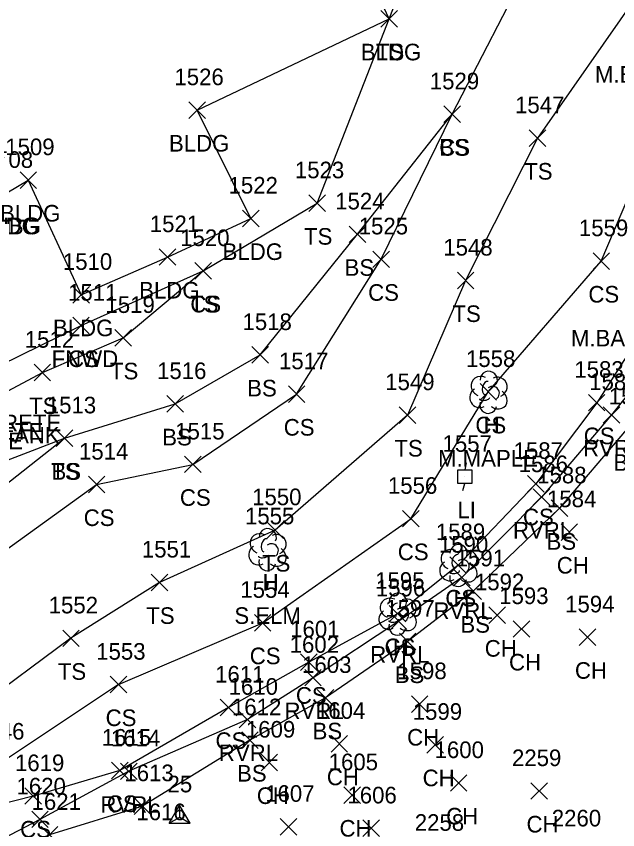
# Model space of a CAD drawing. Extents: x 1504228 to 1506103, y 437717 to 440106.
# Drawn here: x 1505258.5 to 1505331, y 438213.9 to 438311.9 of the extents above; entities that cross this region are included whole.
import ezdxf

# ---------------------------------------------------------------- set-up
doc = ezdxf.new("R2010")
doc.units = 0
for name, color, linetype in [('C_I', 7, 'Continuous'), ('CPSM', 7, 'Continuous'), ('L_A', 7, 'Continuous'), ('L_C', 7, 'Continuous'), ('L_I', 7, 'Continuous'), ('L_TIC', 7, 'Continuous'), ('LAWE', 7, 'Continuous'), ('LBC', 7, 'Continuous'), ('LELB', 7, 'Continuous'), ('LFNC', 7, 'Continuous'), ('LTD', 7, 'Continuous'), ('R_C', 7, 'Continuous'), ('U_A', 7, 'Continuous'), ('U_I', 7, 'Continuous'), ('ULP', 7, 'Continuous')]:
    doc.layers.add(name, color=color, linetype=linetype)

msp = doc.modelspace()

# ---------------------------------------------------------------- linework, layer by layer
at = {"layer": 'CPSM'}
for p, q in [((1505276.915, 438214.672), (1505278.165, 438216.837)), ((1505279.415, 438214.672), (1505278.165, 438216.837)), ((1505278.166, 438215.393), (1505278.165, 438216.837)), ((1505276.915, 438214.672), (1505278.166, 438215.393)), ((1505276.915, 438214.672), (1505279.415, 438214.672)), ((1505278.166, 438215.393), (1505278.166, 438215.393)), ((1505278.166, 438215.393), (1505279.415, 438214.672))]:
    msp.add_line(p, q, dxfattribs=at)
at = {"layer": 'L_TIC'}
for points in [[(1505302.41, 438310.599), (1505304.41, 438312.599)], [(1505304.41, 438310.599), (1505302.41, 438312.599)], [(1505302.41, 438310.599), (1505304.41, 438312.599)], [(1505304.41, 438310.599), (1505302.41, 438312.599)], [(1505279.282, 438299.604), (1505281.282, 438301.604)], [(1505281.282, 438299.604), (1505279.282, 438301.604)], [(1505310.019, 438299.105), (1505312.019, 438301.105)], [(1505312.019, 438299.105), (1505310.019, 438301.105)], [(1505310.019, 438299.105), (1505312.019, 438301.105)], [(1505312.019, 438299.105), (1505310.019, 438301.105)], [(1505320.287, 438296.225), (1505322.287, 438298.225)], [(1505322.287, 438296.225), (1505320.287, 438298.225)], [(1505258.92, 438291.172), (1505260.92, 438293.172)], [(1505260.92, 438291.172), (1505258.92, 438293.172)], [(1505293.747, 438288.385), (1505295.747, 438290.385)], [(1505295.747, 438288.385), (1505293.747, 438290.385)], [(1505285.75, 438286.544), (1505287.75, 438288.544)], [(1505287.75, 438286.544), (1505285.75, 438288.544)], [(1505298.605, 438284.634), (1505300.605, 438286.634)], [(1505300.605, 438284.634), (1505298.605, 438286.634)], [(1505275.691, 438281.896), (1505277.691, 438283.896)], [(1505277.691, 438281.896), (1505275.691, 438283.896)], [(1505301.441, 438281.622), (1505303.441, 438283.622)], [(1505303.441, 438281.622), (1505301.441, 438283.622)], [(1505327.992, 438281.411), (1505329.992, 438283.411)], [(1505329.992, 438281.411), (1505327.992, 438283.411)], [(1505280.008, 438280.222), (1505282.008, 438282.222)], [(1505282.008, 438280.222), (1505280.008, 438282.222)], [(1505280.008, 438280.222), (1505282.008, 438282.222)], [(1505282.008, 438280.222), (1505280.008, 438282.222)], [(1505311.638, 438279.068), (1505313.638, 438281.068)], [(1505313.638, 438279.068), (1505311.638, 438281.068)], [(1505265.3, 438277.353), (1505267.3, 438279.353)], [(1505267.3, 438277.353), (1505265.3, 438279.353)], [(1505265.273, 438273.64), (1505267.273, 438275.64)], [(1505267.273, 438273.64), (1505265.273, 438275.64)], [(1505265.273, 438273.64), (1505267.273, 438275.64)], [(1505267.273, 438273.64), (1505265.273, 438275.64)], [(1505270.354, 438272.157), (1505272.354, 438274.157)], [(1505272.354, 438272.157), (1505270.354, 438274.157)], [(1505286.866, 438270.097), (1505288.866, 438272.097)], [(1505288.866, 438270.097), (1505286.866, 438272.097)], [(1505260.614, 438267.97), (1505262.614, 438269.97)], [(1505262.614, 438267.97), (1505260.614, 438269.97)], [(1505314.372, 438265.647), (1505316.372, 438267.647)], [(1505316.372, 438265.647), (1505314.372, 438267.647)], [(1505291.268, 438265.376), (1505293.268, 438267.376)], [(1505293.268, 438265.376), (1505291.268, 438267.376)], [(1505276.623, 438264.195), (1505278.623, 438266.195)], [(1505278.623, 438264.195), (1505276.623, 438266.195)], [(1505327.434, 438264.347), (1505329.434, 438266.347)], [(1505329.434, 438264.347), (1505327.434, 438266.347)], [(1505304.643, 438262.855), (1505306.643, 438264.855)], [(1505306.643, 438262.855), (1505304.643, 438264.855)], [(1505329.226, 438262.864), (1505331.226, 438264.864)], [(1505331.226, 438262.864), (1505329.226, 438264.864)], [(1505263.276, 438260.061), (1505265.276, 438262.061)], [(1505265.276, 438260.061), (1505263.276, 438262.061)], [(1505263.276, 438260.061), (1505265.276, 438262.061)], [(1505265.276, 438260.061), (1505263.276, 438262.061)], [(1505278.753, 438256.916), (1505280.753, 438258.916)], [(1505280.753, 438256.916), (1505278.753, 438258.916)], [(1505267.157, 438254.486), (1505269.157, 438256.486)], [(1505269.157, 438254.486), (1505267.157, 438256.486)], [(1505320.109, 438254.57), (1505322.109, 438256.57)], [(1505322.109, 438254.57), (1505320.109, 438256.57)], [(1505320.774, 438252.978), (1505322.774, 438254.978)], [(1505322.774, 438252.978), (1505320.774, 438254.978)], [(1505322.954, 438251.628), (1505324.954, 438253.628)], [(1505324.954, 438251.628), (1505322.954, 438253.628)], [(1505305.017, 438250.366), (1505307.017, 438252.366)], [(1505307.017, 438250.366), (1505305.017, 438252.366)], [(1505288.682, 438248.994), (1505290.682, 438250.994)], [(1505290.682, 438248.994), (1505288.682, 438250.994)], [(1505324.135, 438248.753), (1505326.135, 438250.753)], [(1505326.135, 438248.753), (1505324.135, 438250.753)], [(1505310.747, 438244.782), (1505312.747, 438246.782)], [(1505312.747, 438244.782), (1505310.747, 438246.782)], [(1505311.194, 438243.278), (1505313.194, 438245.278)], [(1505313.194, 438243.278), (1505311.194, 438245.278)], [(1505274.731, 438242.689), (1505276.731, 438244.689)], [(1505276.731, 438242.689), (1505274.731, 438244.689)], [(1505312.563, 438241.629), (1505314.563, 438243.629)], [(1505314.563, 438241.629), (1505312.563, 438243.629)], [(1505303.42, 438238.919), (1505305.42, 438240.919)], [(1505305.42, 438238.919), (1505303.42, 438240.919)], [(1505303.566, 438238.011), (1505305.566, 438240.011)], [(1505305.566, 438238.011), (1505303.566, 438240.011)], [(1505315.449, 438238.742), (1505317.449, 438240.742)], [(1505317.449, 438238.742), (1505315.449, 438240.742)], [(1505287.172, 438237.832), (1505289.172, 438239.832)], [(1505289.172, 438237.832), (1505287.172, 438239.832)], [(1505318.376, 438237.075), (1505320.376, 438239.075)], [(1505320.376, 438237.075), (1505318.376, 438239.075)], [(1505326.323, 438236.077), (1505328.323, 438238.077)], [(1505328.323, 438236.077), (1505326.323, 438238.077)], [(1505264.066, 438235.954), (1505266.066, 438237.954)], [(1505266.066, 438235.954), (1505264.066, 438237.954)], [(1505304.646, 438235.558), (1505306.646, 438237.558)], [(1505306.646, 438235.558), (1505304.646, 438237.558)], [(1505292.736, 438233.076), (1505294.736, 438235.076)], [(1505294.736, 438233.076), (1505292.736, 438235.076)], [(1505293.241, 438231.21), (1505295.241, 438233.21)], [(1505295.241, 438231.21), (1505293.241, 438233.21)], [(1505269.798, 438230.377), (1505271.798, 438232.377)], [(1505271.798, 438230.377), (1505269.798, 438232.377)], [(1505269.798, 438230.377), (1505271.798, 438232.377)], [(1505271.798, 438230.377), (1505269.798, 438232.377)], [(1505294.746, 438228.78), (1505296.746, 438230.78)], [(1505296.746, 438228.78), (1505294.746, 438230.78)], [(1505283.045, 438227.619), (1505285.045, 438229.619)], [(1505285.045, 438227.619), (1505283.045, 438229.619)], [(1505306.096, 438228.028), (1505308.096, 438230.028)], [(1505308.096, 438228.028), (1505306.096, 438230.028)], [(1505285.327, 438226.151), (1505287.327, 438228.151)], [(1505287.327, 438226.151), (1505285.327, 438228.151)], [(1505285.64, 438223.685), (1505287.64, 438225.685)], [(1505287.64, 438223.685), (1505285.64, 438225.685)], [(1505296.415, 438223.25), (1505298.415, 438225.25)], [(1505298.415, 438223.25), (1505296.415, 438225.25)], [(1505307.962, 438223.13), (1505309.962, 438225.13)], [(1505309.962, 438223.13), (1505307.962, 438225.13)], [(1505287.976, 438220.99), (1505289.976, 438222.99)], [(1505289.976, 438220.99), (1505287.976, 438222.99)], [(1505269.947, 438220.02), (1505271.947, 438222.02)], [(1505271.947, 438220.02), (1505269.947, 438222.02)], [(1505271.047, 438219.927), (1505273.047, 438221.927)], [(1505273.047, 438219.927), (1505271.047, 438221.927)], [(1505310.8, 438218.522), (1505312.8, 438220.522)], [(1505312.8, 438218.522), (1505310.8, 438220.522)], [(1505320.491, 438217.554), (1505322.491, 438219.554)], [(1505322.491, 438217.554), (1505320.491, 438219.554)], [(1505259.492, 438216.948), (1505261.492, 438218.948)], [(1505261.492, 438216.948), (1505259.492, 438218.948)], [(1505297.947, 438217.058), (1505299.947, 438219.058)], [(1505299.947, 438217.058), (1505297.947, 438219.058)], [(1505272.677, 438215.738), (1505274.677, 438217.738)], [(1505274.677, 438215.738), (1505272.677, 438217.738)], [(1505260.327, 438214.137), (1505262.327, 438216.137)], [(1505262.327, 438214.137), (1505260.327, 438216.137)], [(1505290.292, 438213.251), (1505292.292, 438215.251)], [(1505292.292, 438213.251), (1505290.292, 438215.251)], [(1505300.263, 438213.06), (1505302.263, 438215.06)], [(1505302.263, 438213.06), (1505300.263, 438215.06)], [(1505261.485, 438212.279), (1505263.485, 438214.279)], [(1505263.485, 438212.279), (1505261.485, 438214.279)]]:
    msp.add_lwpolyline(points, dxfattribs=at)
at = {"layer": 'LAWE'}
msp.add_lwpolyline([(1505362.196, 438317.813), (1505351.384, 438297.395), (1505340.369, 438276.571), (1505330.226, 438263.864), (1505321.774, 438253.978), (1505312.194, 438244.278), (1505304.566, 438239.011), (1505294.241, 438232.21), (1505286.327, 438227.151), (1505272.047, 438220.927), (1505261.327, 438215.137), (1505255.057, 438211.857), (1505252.998, 438208.079)], dxfattribs=at)
at = {"layer": 'LBC'}
for points in [[(1505291.942, 438336.147), (1505251.464, 438317.946), (1505221.324, 438304.226), (1505215.361, 438301.39), (1505212.864, 438300.095), (1505216.768, 438291.382), (1505219.713, 438285.085), (1505224.136, 438275.747), (1505225.84, 438276.507), (1505226.05, 438276.605), (1505237.288, 438281.504), (1505257.323, 438290.638), (1505259.92, 438292.172), (1505266.3, 438278.353), (1505276.691, 438282.896), (1505286.75, 438287.544), (1505280.282, 438300.604), (1505303.41, 438311.599)], [(1505303.41, 438311.599), (1505291.942, 438336.147)]]:
    msp.add_lwpolyline(points, dxfattribs=at)
at = {"layer": 'LELB'}
for points in [[(1505345.996, 438335.597), (1505333.305, 438314.456), (1505321.287, 438297.225), (1505312.638, 438280.068), (1505305.643, 438263.855), (1505289.682, 438249.994), (1505275.731, 438243.689), (1505265.066, 438236.954), (1505253.57, 438228.442), (1505232.624, 438230.462), (1505221.792, 438235.116), (1505209.888, 438231.849), (1505203.313, 438230.133), (1505201.377, 438228.793), (1505195.715, 438225.539), (1505189.868, 438221.089), (1505181.214, 438212.467), (1505175.582, 438209.995), (1505180.422, 438196.297), (1505183.694, 438188.776), (1505173.648, 438207.305)], [(1505219.873, 438244.656), (1505224.212, 438246.435), (1505223.766, 438248.658), (1505222.665, 438251.446), (1505223.309, 438252.491), (1505228.977, 438251.314), (1505233.483, 438250.354), (1505246.941, 438254.407), (1505264.276, 438261.061), (1505277.623, 438265.195), (1505287.866, 438271.097), (1505299.605, 438285.634), (1505311.019, 438300.105), (1505320.782, 438319.021), (1505313.405, 438323.793)], [(1505270.798, 438231.377), (1505288.172, 438238.832), (1505306.017, 438251.366), (1505315.372, 438266.647), (1505328.992, 438282.411), (1505336.428, 438299.931), (1505351.563, 438320.448)], [(1505233.952, 438258.183), (1505245.998, 438260.651), (1505261.614, 438268.97), (1505271.354, 438273.157), (1505281.008, 438281.222), (1505294.747, 438289.385), (1505303.41, 438311.599), (1505306.612, 438319.703)], [(1505357.525, 438320.193), (1505347.775, 438299.58), (1505338.033, 438280.312), (1505328.434, 438265.347), (1505321.109, 438255.57), (1505311.747, 438245.782), (1505304.42, 438239.919), (1505293.736, 438234.076), (1505284.045, 438228.619), (1505270.947, 438221.02), (1505260.492, 438217.948), (1505254.014, 438216.283), (1505247.096, 438215.294)], [(1505365.146, 438316.099), (1505353.966, 438296.236), (1505341.915, 438275.153), (1505332.016, 438262.134), (1505323.954, 438252.628), (1505313.563, 438242.629), (1505305.646, 438236.558), (1505295.746, 438229.78), (1505286.64, 438224.685), (1505273.677, 438216.738), (1505262.485, 438213.279), (1505253.251, 438208.207), (1505250.962, 438202.759), (1505231.919, 438194.06), (1505223.449, 438190.476), (1505215.829, 438187.003), (1505207.689, 438183.331), (1505196.859, 438178.456)], [(1505235.748, 438236.802), (1505242.664, 438237.383), (1505254.364, 438245.583), (1505268.157, 438255.486), (1505279.753, 438257.916), (1505292.268, 438266.376), (1505302.441, 438282.622), (1505311.019, 438300.105)], [(1505266.273, 438274.64), (1505281.008, 438281.222)], [(1505223.309, 438252.491), (1505227.799, 438248.588), (1505237.65, 438245.754), (1505249.505, 438249.429), (1505264.276, 438261.061)], [(1505270.798, 438231.377), (1505256.305, 438221.751), (1505239.591, 438224.256), (1505218.796, 438213.879), (1505204.191, 438212.28), (1505197.941, 438215.08), (1505180.455, 438206.428)]]:
    msp.add_lwpolyline(points, dxfattribs=at)
at = {"layer": 'LFNC'}
msp.add_lwpolyline([(1505252.995, 438271.82), (1505254.064, 438268.642), (1505266.273, 438274.64)], dxfattribs=at)
at = {"layer": 'LTD'}
for p, q in [((1505315.372, 438266.647), (1505315.372, 438266.647)), ((1505315.372, 438266.647), (1505315.372, 438266.647)), ((1505288.732, 438247.689), (1505288.732, 438247.689)), ((1505288.732, 438247.689), (1505288.732, 438247.689)), ((1505311.747, 438245.782), (1505311.747, 438245.782)), ((1505311.747, 438245.782), (1505311.747, 438245.782)), ((1505304.42, 438239.919), (1505304.42, 438239.919)), ((1505304.42, 438239.919), (1505304.42, 438239.919))]:
    msp.add_line(p, q, dxfattribs=at)
for centre in [(1505315.419, 438268.081), (1505288.779, 438249.123), (1505311.793, 438247.216), (1505304.466, 438241.353)]:
    msp.add_arc(centre, 1.047, 335.52715, 180.95627, dxfattribs=at)
for centre, major_axis, ratio, start_param, end_param in [((1505314.581, 438267.313), (1.21, -0.512), 0.895232, 1.570796, 4.712389), ((1505316.414, 438267.23), (-1.141, -0.483), 0.949671, 1.570796, 4.712389), ((1505315.164, 438267.105), (-0.208, -0.792), 0.645439, 3.141593, 6.283185), ((1505314.289, 438265.938), (0.584, -1.042), 0.959034, 3.141593, 6.283185), ((1505315.872, 438266.48), (-0.5, 0.667), 0.989748, 3.141593, 6.283185), ((1505316.373, 438265.814), (-1.09, 0.792), 0.841452, 1.570796, 4.712389), ((1505314.914, 438265.897), (-0.625, -0.083), 0.423636, 0, 3.141593), ((1505315.373, 438265.147), (0.265, 1.061), 0.942809, 1.570796, 4.712389), ((1505287.94, 438248.355), (1.21, -0.512), 0.895232, 1.570796, 4.712389), ((1505288.523, 438248.147), (-0.208, -0.792), 0.645439, 3.141593, 6.283185), ((1505289.773, 438248.272), (-1.141, -0.483), 0.949671, 1.570796, 4.712389), ((1505287.649, 438246.98), (0.584, -1.042), 0.959034, 3.141593, 6.283185), ((1505289.232, 438247.522), (-0.5, 0.667), 0.989748, 3.141593, 6.283185), ((1505288.274, 438246.939), (-0.625, -0.083), 0.423636, 0, 3.141593), ((1505289.732, 438246.856), (-1.09, 0.792), 0.841452, 1.570796, 4.712389), ((1505310.955, 438246.448), (1.21, -0.512), 0.895232, 1.570796, 4.712389), ((1505311.538, 438246.24), (-0.208, -0.792), 0.645439, 3.141593, 6.283185), ((1505312.788, 438246.365), (-1.141, -0.483), 0.949671, 1.570796, 4.712389), ((1505288.732, 438246.189), (0.265, 1.061), 0.942809, 1.570796, 4.712389), ((1505310.664, 438245.073), (0.584, -1.042), 0.959034, 3.141593, 6.283185), ((1505312.247, 438245.615), (-0.5, 0.667), 0.989748, 3.141593, 6.283185), ((1505311.289, 438245.032), (-0.625, -0.083), 0.423636, 0, 3.141593), ((1505312.747, 438244.949), (-1.09, 0.792), 0.841452, 1.570796, 4.712389), ((1505311.747, 438244.282), (0.265, 1.061), 0.942809, 1.570796, 4.712389), ((1505303.628, 438240.585), (1.21, -0.512), 0.895232, 1.570796, 4.712389), ((1505304.211, 438240.377), (-0.208, -0.792), 0.645439, 3.141593, 6.283185), ((1505305.461, 438240.502), (-1.141, -0.483), 0.949671, 1.570796, 4.712389), ((1505303.337, 438239.21), (0.584, -1.042), 0.959034, 3.141593, 6.283185), ((1505304.92, 438239.752), (-0.5, 0.667), 0.989748, 3.141593, 6.283185), ((1505303.962, 438239.169), (-0.625, -0.083), 0.423636, 0, 3.141593), ((1505305.42, 438239.085), (-1.09, 0.792), 0.841452, 1.570796, 4.712389), ((1505304.42, 438238.419), (0.265, 1.061), 0.942809, 1.570796, 4.712389)]:
    msp.add_ellipse(centre, major_axis=major_axis, ratio=ratio, start_param=start_param, end_param=end_param, dxfattribs=at)
at = {"layer": 'ULP'}
for p, q in [((1505312.71, 438258.092), (1505312.543, 438257.259)), ((1505311.71, 438255.592), (1505311.71, 438257.259)), ((1505311.71, 438257.259), (1505313.376, 438257.259)), ((1505313.376, 438257.259), (1505313.376, 438255.592)), ((1505312.543, 438256.426), (1505312.543, 438256.426)), ((1505313.376, 438255.592), (1505311.71, 438255.592)), ((1505312.293, 438254.759), (1505312.543, 438255.592))]:
    msp.add_line(p, q, dxfattribs=at)

# ---------------------------------------------------------------- texts
at = {"layer": 'C_I'}
msp.add_text('25', height=2, dxfattribs=at).set_placement((1505276.701, 438218.393))
at = {"layer": 'L_A'}
for s, p in [('BLDG', (1505300, 438306.599)), ('TS', (1505301.819, 438306.599)), ('BLDG', (1505276.873, 438295.604)), ('CS', (1505309.46, 438295.105)), ('BS', (1505309.46, 438295.105)), ('TS', (1505319.697, 438292.225)), ('BLDG', (1505256.511, 438287.172)), ('BLDG', (1505253.914, 438285.638)), ('TS', (1505293.156, 438284.385)), ('BLDG', (1505283.341, 438282.544)), ('BS', (1505298.046, 438280.634)), ('BLDG', (1505273.282, 438277.896)), ('CS', (1505300.882, 438277.622)), ('CS', (1505327.433, 438277.411)), ('TS', (1505279.417, 438276.222)), ('CS', (1505279.449, 438276.222)), ('TS', (1505311.047, 438275.068)), ('BLDG', (1505262.891, 438273.353)), ('FNWD', (1505262.737, 438269.64)), ('CS', (1505264.714, 438269.64)), ('TS', (1505269.763, 438268.157)), ('BS', (1505286.307, 438266.097)), ('TS', (1505260.023, 438263.97)), ('CS', (1505313.813, 438261.647)), ('H', (1505314.806, 438261.647)), ('CS', (1505290.709, 438261.376)), ('BS', (1505276.064, 438260.195)), ('CS', (1505326.875, 438260.347)), ('TS', (1505304.053, 438258.855)), ('RVRL', (1505326.793, 438258.864)), ('BS', (1505330.457, 438257.134)), ('TS', (1505262.685, 438256.061)), ('BS', (1505262.717, 438256.061)), ('CS', (1505278.194, 438252.916)), ('CS', (1505266.598, 438250.486)), ('CS', (1505319.55, 438250.57)), ('RVRL', (1505318.341, 438248.978)), ('BS', (1505322.395, 438247.628)), ('CS', (1505304.458, 438246.366)), ('TS', (1505288.091, 438244.994)), ('CH', (1505323.623, 438244.753)), ('H', (1505288.165, 438242.689)), ('CS', (1505310.188, 438240.782)), ('H', (1505311.18, 438240.782)), ('RVRL', (1505308.761, 438239.278)), ('TS', (1505274.14, 438238.689)), ('BS', (1505312.004, 438237.629)), ('CS', (1505302.861, 438234.919)), ('H', (1505303.853, 438234.919)), ('CH', (1505314.937, 438234.742)), ('CS', (1505286.613, 438233.832)), ('RVRL', (1505301.133, 438234.011)), ('CH', (1505317.864, 438233.075)), ('TS', (1505263.475, 438231.954)), ('BS', (1505304.087, 438231.558)), ('CH', (1505325.811, 438232.077)), ('CS', (1505292.177, 438229.076)), ('CS', (1505269.239, 438226.377)), ('CS', (1505269.239, 438226.377)), ('RVRL', (1505290.808, 438227.21)), ('BS', (1505294.187, 438224.78)), ('CS', (1505282.486, 438223.619)), ('CH', (1505305.584, 438224.028)), ('RVRL', (1505282.894, 438222.151)), ('BS', (1505285.081, 438219.685)), ('CH', (1505295.904, 438219.25)), ('CH', (1505307.45, 438219.13)), ('CH', (1505287.465, 438216.99)), ('RVRL', (1505268.613, 438215.927)), ('CS', (1505269.388, 438216.02)), ('CH', (1505310.288, 438214.522)), ('CH', (1505319.98, 438213.554)), ('CS', (1505258.933, 438212.948)), ('CH', (1505297.435, 438213.058))]:
    msp.add_text(s, height=2, dxfattribs=at).set_placement(p)
at = {"layer": 'L_C'}
for s, p in [('M.BOXELDER', (1505328.229, 438303.898)), ('M.BASSWOOD', (1505325.327, 438272.123)), ('PROPANE TANK', (1505242.754, 438260.433)), ('M.MAPLE', (1505309.309, 438257.647)), ('S.ELM', (1505284.763, 438238.689))]:
    msp.add_text(s, height=2, dxfattribs=at).set_placement(p)
at = {"layer": 'L_I'}
for s, p in [('1526', (1505277.534, 438303.604)), ('1529', (1505308.318, 438303.105)), ('1529', (1505308.318, 438303.105)), ('1547', (1505318.595, 438300.225)), ('1509', (1505257.141, 438295.172)), ('1508', (1505254.552, 438293.638)), ('1523', (1505292.054, 438292.385)), ('1522', (1505284.057, 438290.544)), ('1524', (1505296.912, 438288.634)), ('1521', (1505274.565, 438285.896)), ('1525', (1505299.748, 438285.622)), ('1559', (1505326.291, 438285.411)), ('1520', (1505278.228, 438284.222)), ('1520', (1505278.228, 438284.222)), ('1548', (1505309.945, 438283.068)), ('1510', (1505264.088, 438281.353)), ('1511', (1505264.714, 438277.64)), ('1511', (1505264.714, 438277.64)), ('1519', (1505269.22, 438276.157)), ('1518', (1505285.74, 438274.097)), ('1512', (1505259.488, 438271.97)), ('1517', (1505290.142, 438269.376)), ('1558', (1505312.68, 438269.647)), ('1558', (1505312.68, 438269.647)), ('1516', (1505275.442, 438268.195)), ('1583', (1505325.741, 438268.347)), ('1549', (1505302.942, 438266.855)), ('1582', (1505327.533, 438266.864)), ('1581', (1505329.89, 438265.134)), ('1513', (1505262.15, 438264.061)), ('1513', (1505262.15, 438264.061)), ('1515', (1505277.627, 438260.916)), ('1587', (1505318.416, 438258.57)), ('1514', (1505266.031, 438258.486)), ('1586', (1505319.026, 438256.978)), ('1588', (1505321.261, 438255.628)), ('1556', (1505303.269, 438254.366)), ('1550', (1505286.902, 438252.994)), ('1584', (1505322.442, 438252.753)), ('1555', (1505286.039, 438250.689)), ('1589', (1505309.046, 438248.782)), ('1589', (1505309.046, 438248.782)), ('1590', (1505309.414, 438247.278)), ('1551', (1505273.605, 438246.689)), ('1591', (1505311.437, 438245.629)), ('1595', (1505301.727, 438242.919)), ('1595', (1505301.727, 438242.919)), ('1596', (1505301.818, 438242.011)), ('1592', (1505313.756, 438242.742)), ('1554', (1505285.479, 438241.832)), ('1593', (1505316.683, 438241.075)), ('1552', (1505262.373, 438239.954)), ('1594', (1505324.63, 438240.077)), ('1597', (1505302.953, 438239.558)), ('1601', (1505291.484, 438237.076)), ('1602', (1505291.422, 438235.21)), ('1553', (1505268.105, 438234.377)), ('1553', (1505268.105, 438234.377)), ('1603', (1505292.927, 438232.78)), ('1611', (1505282.438, 438231.619)), ('1598', (1505304.403, 438232.028)), ('1610', (1505284.067, 438230.151)), ('1612', (1505284.467, 438227.685)), ('1604', (1505294.596, 438227.25)), ('1599', (1505306.261, 438227.13)), ('1646', (1505253.51, 438224.751)), ('1609', (1505286.15, 438224.99)), ('1615', (1505268.773, 438224.02)), ('1614', (1505269.873, 438223.927)), ('1600', (1505308.894, 438222.522)), ('2259', (1505318.224, 438221.554)), ('1619', (1505258.311, 438220.948)), ('1605', (1505296.128, 438221.058)), ('1613', (1505271.504, 438219.738)), ('1620', (1505258.501, 438218.137)), ('1607', (1505288.474, 438217.251)), ('1606', (1505298.389, 438217.06)), ('1621', (1505260.312, 438216.279)), ('1616', (1505272.945, 438215.035)), ('2258', (1505306.508, 438213.757)), ('2260', (1505323.024, 438214.285))]:
    msp.add_text(s, height=2, dxfattribs=at).set_placement(p)
at = {"layer": 'R_C'}
for p in [(1505235.655, 438261.907), (1505233.499, 438260.878), (1505231.034, 438259.736)]:
    msp.add_text('STEEL W/ CONCRETE', height=2, dxfattribs=at).set_placement(p)
at = {"layer": 'U_A'}
for s, p in [('SUBG', (1505253.851, 438285.638)), ('LI', (1505311.645, 438251.426))]:
    msp.add_text(s, height=2, dxfattribs=at).set_placement(p)
at = {"layer": 'U_I'}
for s, p in [('1508', (1505254.552, 438293.638)), ('1557', (1505309.85, 438259.426))]:
    msp.add_text(s, height=2, dxfattribs=at).set_placement(p)

doc.saveas('drawing.dxf')
